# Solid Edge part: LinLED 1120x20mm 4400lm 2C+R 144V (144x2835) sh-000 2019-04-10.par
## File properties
Author: sylwester.cabaj
Template: iso metric part.par
Last saved by: sylwester.cabaj
Revision: 3
Application: Solid Edge
Gęstość: 0,000 kg/m^3
Dokładność: 0,990
Username: sylwester.cabaj
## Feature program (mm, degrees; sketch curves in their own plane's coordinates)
body "unnamed Body 1"
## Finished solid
Body 1: solid body, 3136 faces, 8187 edges, 5359 vertices.
  Faces by surface: plane 2688, cylinder 217, spline 144, cone 36, sphere 24, torus 15, spun 12
  Edges by curve: line 7252, curve on surface 480, circle 293, ellipse 90, spline 66, intersection 6
Bounding box of the edges (mm; curved faces can reach further): 1120.000 x 5.000 x 20.000, from (-560, -3.4, -10) to (560, 1.6, 10).
Cylindrical faces by radius (mm): R0.2 x69, R0.2169 x9, R0.25 x12, R0.3373 x9, R0.4 x12, R0.4006 x3, R0.4008 x3, R0.525 x3, R0.6 x24, R1 x12, R1.1 x6, R1.2 x15, R2.15 x40
Conical faces (half-angle, radius in mm at the cone's reference point): 0.5 deg R0.5056 x6, 0.5 deg R1.0082 x6, 1 deg R0.5511 x3, 10 deg R0.2132 x6, 10 deg R0.4132 x6, 18.8604 deg R1.0669 x6, 27.363 deg R0.6214 x3
Toroidal faces (ring radius, tube radius in mm): R0.8 r0.2 x6, R0.8522 r0.3 x3, R0.9002 r0.2 x3, R0.9018 r0.2 x3
Spherical faces by radius (mm): R0.2 x18, R0.6 x6
Planar faces by outward normal: +x 349, +y 10, +z 330, -x 354, -y 469, -z 330, oblique 846
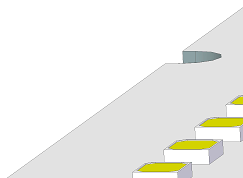
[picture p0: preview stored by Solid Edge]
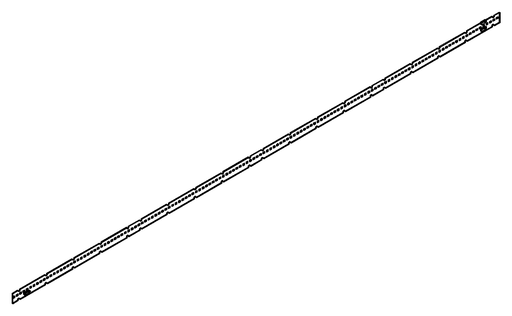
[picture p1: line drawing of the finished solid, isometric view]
